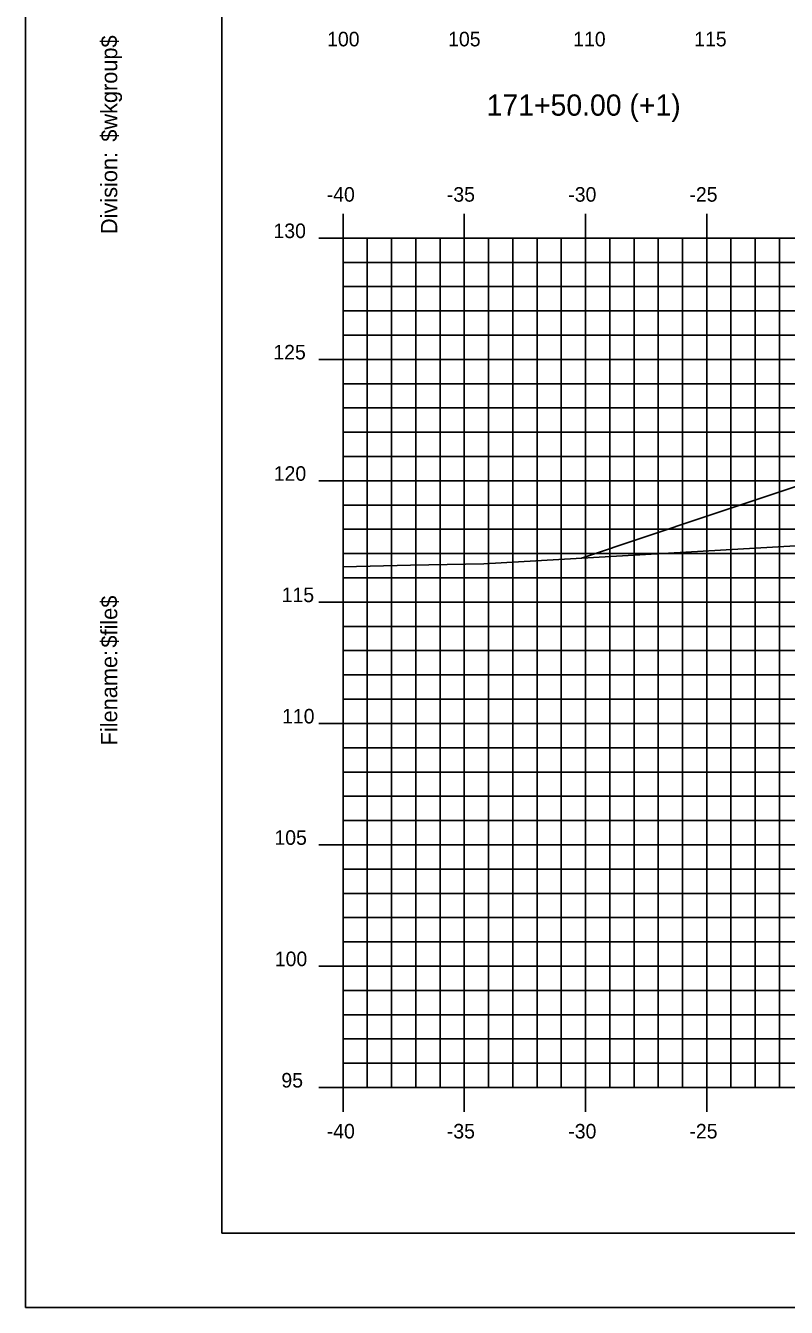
# Model space of a CAD drawing. Extents: x 850598 to 870284, y 366541 to 366651.
# Drawn here: x 856141.7 to 856173.1, y 366541.2 to 366594 of the extents above; entities that cross this region are included whole.
import ezdxf

# ---------------------------------------------------------------- set-up
doc = ezdxf.new("R2010")
doc.units = 0
for name, color, linetype in [('BORDER', 7, 'Continuous'), ('D_Roadway_Centerline', 7, 'Continuous'), ('D_Roadway_SlopeLines', 7, 'Continuous'), ('H_V ANNOTATION', 7, 'Continuous'), ('MAJOR', 7, 'Continuous'), ('MINOR', 7, 'Continuous'), ('PLOT BOUNDARY', 7, 'Continuous'), ('S_Roadway_Centerline', 7, 'Continuous')]:
    doc.layers.add(name, color=color, linetype=linetype)

msp = doc.modelspace()

# ---------------------------------------------------------------- linework, layer by layer
at = {"layer": 'BORDER'}
for p, q in [((856149.811, 366649.225), (856149.811, 366544.225)), ((856149.811, 366544.225), (856309.811, 366544.225))]:
    msp.add_line(p, q, dxfattribs=at)
at = {"layer": 'D_Roadway_Centerline'}
msp.add_lwpolyline([(856164.64, 366572.038), (856169.811, 366573.762), (856173.613, 366575.029), (856179.811, 366577.095), (856183.811, 366577.335), (856194.811, 366577.665), (856205.811, 366577.335), (856209.811, 366577.095), (856211.811, 366576.975), (856217.811, 366574.975), (856270.299, 366563.225), (856287.24, 366559.433), (856294.811, 366557.738)], dxfattribs=at)
at = {"layer": 'D_Roadway_SlopeLines'}
for points in [[(856183.811, 366577.335), (856179.811, 366577.095), (856169.811, 366573.762)], [(856169.811, 366573.762), (856164.64, 366572.038)]]:
    msp.add_lwpolyline(points, dxfattribs=at)
at = {"layer": 'MAJOR'}
for p, q in [((856154.811, 366586.227), (856154.811, 366585.225)), ((856154.811, 366586.227), (856154.811, 366585.225)), ((856159.811, 366586.227), (856159.811, 366585.225)), ((856159.811, 366586.227), (856159.811, 366585.225)), ((856164.811, 366586.227), (856164.811, 366585.225)), ((856164.811, 366586.227), (856164.811, 366585.225)), ((856169.811, 366586.227), (856169.811, 366585.225)), ((856169.811, 366586.227), (856169.811, 366585.225)), ((856153.809, 366585.225), (856154.811, 366585.225)), ((856153.809, 366585.225), (856154.811, 366585.225)), ((856154.811, 366585.225), (856294.811, 366585.225)), ((856154.811, 366550.225), (856154.811, 366585.225)), ((856154.811, 366550.225), (856154.811, 366585.225)), ((856154.811, 366585.225), (856294.811, 366585.225)), ((856154.811, 366585.225), (856294.811, 366585.225)), ((856154.811, 366550.225), (856154.811, 366585.225)), ((856154.811, 366550.225), (856154.811, 366585.225)), ((856154.811, 366585.225), (856294.811, 366585.225)), ((856159.811, 366550.225), (856159.811, 366585.225)), ((856159.811, 366550.225), (856159.811, 366585.225)), ((856164.811, 366550.225), (856164.811, 366585.225)), ((856164.811, 366550.225), (856164.811, 366585.225)), ((856169.811, 366550.225), (856169.811, 366585.225)), ((856169.811, 366550.225), (856169.811, 366585.225)), ((856153.809, 366580.225), (856154.811, 366580.225)), ((856153.809, 366580.225), (856154.811, 366580.225)), ((856154.811, 366580.225), (856294.811, 366580.225)), ((856154.811, 366580.225), (856294.811, 366580.225)), ((856153.809, 366575.225), (856154.811, 366575.225)), ((856153.809, 366575.225), (856154.811, 366575.225)), ((856154.811, 366575.225), (856294.811, 366575.225)), ((856154.811, 366575.225), (856294.811, 366575.225)), ((856153.809, 366570.225), (856154.811, 366570.225)), ((856153.809, 366570.225), (856154.811, 366570.225)), ((856154.811, 366570.225), (856294.811, 366570.225)), ((856154.811, 366570.225), (856294.811, 366570.225)), ((856153.809, 366565.225), (856154.811, 366565.225)), ((856153.809, 366565.225), (856154.811, 366565.225)), ((856154.811, 366565.225), (856294.811, 366565.225)), ((856154.811, 366565.225), (856294.811, 366565.225)), ((856153.809, 366560.225), (856154.811, 366560.225)), ((856153.809, 366560.225), (856154.811, 366560.225)), ((856154.811, 366560.225), (856294.811, 366560.225)), ((856154.811, 366560.225), (856294.811, 366560.225)), ((856153.809, 366555.225), (856154.811, 366555.225)), ((856153.809, 366555.225), (856154.811, 366555.225)), ((856154.811, 366555.225), (856294.811, 366555.225)), ((856154.811, 366555.225), (856294.811, 366555.225)), ((856153.809, 366550.225), (856154.811, 366550.225)), ((856153.809, 366550.225), (856154.811, 366550.225)), ((856154.811, 366550.225), (856294.811, 366550.225)), ((856154.811, 366550.225), (856294.811, 366550.225)), ((856154.811, 366549.223), (856154.811, 366550.225)), ((856154.811, 366550.225), (856294.811, 366550.225)), ((856154.811, 366550.225), (856294.811, 366550.225)), ((856154.811, 366549.223), (856154.811, 366550.225)), ((856159.811, 366549.223), (856159.811, 366550.225)), ((856159.811, 366549.223), (856159.811, 366550.225)), ((856164.811, 366549.223), (856164.811, 366550.225)), ((856164.811, 366549.223), (856164.811, 366550.225)), ((856169.811, 366549.223), (856169.811, 366550.225)), ((856169.811, 366549.223), (856169.811, 366550.225))]:
    msp.add_line(p, q, dxfattribs=at)
at = {"layer": 'MINOR'}
for p, q in [((856155.811, 366550.225), (856155.811, 366585.225)), ((856155.811, 366550.225), (856155.811, 366585.225)), ((856156.811, 366550.225), (856156.811, 366585.225)), ((856156.811, 366550.225), (856156.811, 366585.225)), ((856157.811, 366550.225), (856157.811, 366585.225)), ((856157.811, 366550.225), (856157.811, 366585.225)), ((856158.811, 366550.225), (856158.811, 366585.225)), ((856158.811, 366550.225), (856158.811, 366585.225)), ((856160.811, 366550.225), (856160.811, 366585.225)), ((856160.811, 366550.225), (856160.811, 366585.225)), ((856161.811, 366550.225), (856161.811, 366585.225)), ((856161.811, 366550.225), (856161.811, 366585.225)), ((856162.811, 366550.225), (856162.811, 366585.225)), ((856162.811, 366550.225), (856162.811, 366585.225)), ((856163.811, 366550.225), (856163.811, 366585.225)), ((856163.811, 366550.225), (856163.811, 366585.225)), ((856165.811, 366550.225), (856165.811, 366585.225)), ((856165.811, 366550.225), (856165.811, 366585.225)), ((856166.811, 366550.225), (856166.811, 366585.225)), ((856166.811, 366550.225), (856166.811, 366585.225)), ((856167.811, 366550.225), (856167.811, 366585.225)), ((856167.811, 366550.225), (856167.811, 366585.225)), ((856168.811, 366550.225), (856168.811, 366585.225)), ((856168.811, 366550.225), (856168.811, 366585.225)), ((856170.811, 366550.225), (856170.811, 366585.225)), ((856170.811, 366550.225), (856170.811, 366585.225)), ((856171.811, 366550.225), (856171.811, 366585.225)), ((856171.811, 366550.225), (856171.811, 366585.225)), ((856172.811, 366550.225), (856172.811, 366585.225)), ((856172.811, 366550.225), (856172.811, 366585.225)), ((856154.811, 366584.225), (856294.811, 366584.225)), ((856154.811, 366584.225), (856155.813, 366584.225)), ((856154.811, 366584.225), (856294.811, 366584.225)), ((856154.811, 366584.225), (856155.813, 366584.225)), ((856154.811, 366583.225), (856294.811, 366583.225)), ((856154.811, 366583.225), (856155.813, 366583.225)), ((856154.811, 366583.225), (856294.811, 366583.225)), ((856154.811, 366583.225), (856155.813, 366583.225)), ((856154.811, 366582.225), (856294.811, 366582.225)), ((856154.811, 366582.225), (856155.813, 366582.225)), ((856154.811, 366582.225), (856294.811, 366582.225)), ((856154.811, 366582.225), (856155.813, 366582.225)), ((856154.811, 366581.225), (856294.811, 366581.225)), ((856154.811, 366581.225), (856155.813, 366581.225)), ((856154.811, 366581.225), (856294.811, 366581.225)), ((856154.811, 366581.225), (856155.813, 366581.225)), ((856154.811, 366579.225), (856294.811, 366579.225)), ((856154.811, 366579.225), (856155.813, 366579.225)), ((856154.811, 366579.225), (856294.811, 366579.225)), ((856154.811, 366579.225), (856155.813, 366579.225)), ((856154.811, 366578.225), (856294.811, 366578.225)), ((856154.811, 366578.225), (856155.813, 366578.225)), ((856154.811, 366578.225), (856294.811, 366578.225)), ((856154.811, 366578.225), (856155.813, 366578.225)), ((856154.811, 366577.225), (856294.811, 366577.225)), ((856154.811, 366577.225), (856155.813, 366577.225)), ((856154.811, 366577.225), (856294.811, 366577.225)), ((856154.811, 366577.225), (856155.813, 366577.225)), ((856154.811, 366576.225), (856294.811, 366576.225)), ((856154.811, 366576.225), (856155.813, 366576.225)), ((856154.811, 366576.225), (856294.811, 366576.225)), ((856154.811, 366576.225), (856155.813, 366576.225)), ((856154.811, 366574.225), (856294.811, 366574.225)), ((856154.811, 366574.225), (856155.813, 366574.225)), ((856154.811, 366574.225), (856294.811, 366574.225)), ((856154.811, 366574.225), (856155.813, 366574.225)), ((856154.811, 366573.225), (856294.811, 366573.225)), ((856154.811, 366573.225), (856155.813, 366573.225)), ((856154.811, 366573.225), (856294.811, 366573.225)), ((856154.811, 366573.225), (856155.813, 366573.225)), ((856154.811, 366572.225), (856294.811, 366572.225)), ((856154.811, 366572.225), (856155.813, 366572.225)), ((856154.811, 366572.225), (856294.811, 366572.225)), ((856154.811, 366572.225), (856155.813, 366572.225)), ((856154.811, 366571.225), (856294.811, 366571.225)), ((856154.811, 366571.225), (856155.813, 366571.225)), ((856154.811, 366571.225), (856294.811, 366571.225)), ((856154.811, 366571.225), (856155.813, 366571.225)), ((856154.811, 366569.225), (856294.811, 366569.225)), ((856154.811, 366569.225), (856155.813, 366569.225)), ((856154.811, 366569.225), (856294.811, 366569.225)), ((856154.811, 366569.225), (856155.813, 366569.225)), ((856154.811, 366568.225), (856294.811, 366568.225)), ((856154.811, 366568.225), (856155.813, 366568.225)), ((856154.811, 366568.225), (856294.811, 366568.225)), ((856154.811, 366568.225), (856155.813, 366568.225)), ((856154.811, 366567.225), (856294.811, 366567.225)), ((856154.811, 366567.225), (856155.813, 366567.225)), ((856154.811, 366567.225), (856294.811, 366567.225)), ((856154.811, 366567.225), (856155.813, 366567.225)), ((856154.811, 366566.225), (856294.811, 366566.225)), ((856154.811, 366566.225), (856155.813, 366566.225)), ((856154.811, 366566.225), (856294.811, 366566.225)), ((856154.811, 366566.225), (856155.813, 366566.225)), ((856154.811, 366564.225), (856294.811, 366564.225)), ((856154.811, 366564.225), (856155.813, 366564.225)), ((856154.811, 366564.225), (856294.811, 366564.225)), ((856154.811, 366564.225), (856155.813, 366564.225)), ((856154.811, 366563.225), (856294.811, 366563.225)), ((856154.811, 366563.225), (856155.813, 366563.225)), ((856154.811, 366563.225), (856294.811, 366563.225)), ((856154.811, 366563.225), (856155.813, 366563.225)), ((856154.811, 366562.225), (856294.811, 366562.225)), ((856154.811, 366562.225), (856155.813, 366562.225)), ((856154.811, 366562.225), (856294.811, 366562.225)), ((856154.811, 366562.225), (856155.813, 366562.225)), ((856154.811, 366561.225), (856294.811, 366561.225)), ((856154.811, 366561.225), (856155.813, 366561.225)), ((856154.811, 366561.225), (856294.811, 366561.225)), ((856154.811, 366561.225), (856155.813, 366561.225)), ((856154.811, 366559.225), (856294.811, 366559.225)), ((856154.811, 366559.225), (856155.813, 366559.225)), ((856154.811, 366559.225), (856294.811, 366559.225)), ((856154.811, 366559.225), (856155.813, 366559.225)), ((856154.811, 366558.225), (856294.811, 366558.225)), ((856154.811, 366558.225), (856155.813, 366558.225)), ((856154.811, 366558.225), (856294.811, 366558.225)), ((856154.811, 366558.225), (856155.813, 366558.225)), ((856154.811, 366557.225), (856294.811, 366557.225)), ((856154.811, 366557.225), (856155.813, 366557.225)), ((856154.811, 366557.225), (856294.811, 366557.225)), ((856154.811, 366557.225), (856155.813, 366557.225)), ((856154.811, 366556.225), (856294.811, 366556.225)), ((856154.811, 366556.225), (856155.813, 366556.225)), ((856154.811, 366556.225), (856294.811, 366556.225)), ((856154.811, 366556.225), (856155.813, 366556.225)), ((856154.811, 366554.225), (856294.811, 366554.225)), ((856154.811, 366554.225), (856155.813, 366554.225)), ((856154.811, 366554.225), (856294.811, 366554.225)), ((856154.811, 366554.225), (856155.813, 366554.225)), ((856154.811, 366553.225), (856294.811, 366553.225)), ((856154.811, 366553.225), (856155.813, 366553.225)), ((856154.811, 366553.225), (856294.811, 366553.225)), ((856154.811, 366553.225), (856155.813, 366553.225)), ((856154.811, 366552.225), (856294.811, 366552.225)), ((856154.811, 366552.225), (856155.813, 366552.225)), ((856154.811, 366552.225), (856294.811, 366552.225)), ((856154.811, 366552.225), (856155.813, 366552.225)), ((856154.811, 366551.225), (856294.811, 366551.225)), ((856154.811, 366551.225), (856155.813, 366551.225)), ((856154.811, 366551.225), (856294.811, 366551.225)), ((856154.811, 366551.225), (856155.813, 366551.225))]:
    msp.add_line(p, q, dxfattribs=at)
at = {"layer": 'PLOT BOUNDARY'}
msp.add_lwpolyline([(856141.717, 366541.166), (856311.717, 366541.166), (856311.717, 366651.166), (856141.717, 366651.166)], close=True, dxfattribs=at)
at = {"layer": 'S_Roadway_Centerline'}
msp.add_lwpolyline([(856154.811, 366571.677), (856157.593, 366571.744), (856160.622, 366571.807), (856180.142, 366572.931), (856200.167, 366574.08), (856200.186, 366574.107), (856200.768, 366574.044), (856204.939, 366573.53), (856213.515, 366575.345), (856214.85, 366575.621), (856216.778, 366575.916), (856218.835, 366576.226)], dxfattribs=at)

# ---------------------------------------------------------------- texts
at = {"layer": 'BORDER'}
for s, p in [('$wkgroup$', (856145.496, 366589.195)), ('Division:', (856145.496, 366585.391)), ('$file$', (856145.496, 366568.351)), ('Filename:', (856145.496, 366564.324))]:
    msp.add_text(s, height=0.6696, rotation=90, dxfattribs=at).set_placement(p)
at = {"layer": 'H_V ANNOTATION'}
for s, height, p in [('100', 0.6, (856154.152, 366593.125)), ('105', 0.6, (856159.144, 366593.125)), ('110', 0.6, (856164.302, 366593.125)), ('115', 0.6, (856169.294, 366593.125)), ('171+50.00 (+1)', 0.87498, (856160.734, 366590.268)), ('-40', 0.6, (856154.136, 366586.725)), ('-35', 0.6, (856159.091, 366586.725)), ('-30', 0.6, (856164.099, 366586.725)), ('-25', 0.6, (856169.096, 366586.725)), ('130', 0.6, (856151.94, 366585.225)), ('125', 0.6, (856151.935, 366580.225)), ('120', 0.6, (856151.951, 366575.225)), ('115', 0.6, (856152.278, 366570.225)), ('110', 0.6, (856152.294, 366565.225)), ('105', 0.6, (856151.978, 366560.225)), ('100', 0.6, (856151.994, 366555.225)), ('95', 0.6, (856152.267, 366550.225)), ('-40', 0.6, (856154.136, 366548.125)), ('-35', 0.6, (856159.091, 366548.125)), ('-30', 0.6, (856164.099, 366548.125)), ('-25', 0.6, (856169.096, 366548.125))]:
    msp.add_text(s, height=height, dxfattribs=at).set_placement(p)

doc.saveas('drawing.dxf')
